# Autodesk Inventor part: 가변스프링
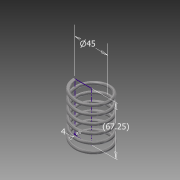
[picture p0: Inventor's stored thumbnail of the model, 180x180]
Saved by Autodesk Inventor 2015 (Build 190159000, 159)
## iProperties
Created: 2016-02
Part Number: 가변스프링
Material: 스테인레스 스틸
Document SubType Name: Modeling
Designer: Administrator
Density: 8 g/cm^3
Appearance: 반연마
Mass: 84.1995 g
Surface Area: 106.448 cm^2
Volume: 10.5249 cm^3
Author: Administrator
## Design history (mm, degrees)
sketch "스케치1"
  geometry: L1 (0, 0)-(22.5, 0); L2 (22.5, 0)-(22.5, 67.25); L3 (22.5, 67.25)-(0, 67.25); L4 (0, 67.25)-(0, 0); C1 r 2 at (22.5, 0)
  constraints: 8 end point, 2 parallel, 1 centre point, 1 coincident, 1 horizontal, 1 perpendicular
  dimensions: "d3" = 45 diameter of L2 L4; "d4" = 67.25 distance between parallel lines of L1 L3 (derived); "d5" = 4 diameter of C1
feature "코일1" sketch "스케치1" pitch "d6" = 10; turns "d8" = 6; dims "d7" = 67.25 (= d4), "d9" = 0, angle "d10" = 90 deg, angle "d11" = 90 deg, "d12" = 0, "d13" = 0
sketch "스케치2"
  geometry: L1 (-20.5, 0)-(-24.5, 0) reference; 1 further point
  constraints: 1 horizontal alignment
extrude "돌출1" cut sketch "스케치2" stored distance "d14" = 10; taper "d15" = 0 deg
node "작업 평면1"
sketch "스케치3"
  geometry: L1 (-2, 0)-(2, 0) reference; 1 further point
  constraints: 1 horizontal alignment
extrude "돌출2" cut sketch "스케치3" stored distance "d16" = 10; taper "d17" = 0 deg
node "솔리드1"
node "절단 모서리 투영1"
node "절단 모서리 투영2"
